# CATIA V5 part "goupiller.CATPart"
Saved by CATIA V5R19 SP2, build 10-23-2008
Part number: Pièce1
Bounding box of the stored display mesh (mm): x 0 to 60, y -7.5 to 7.5, z -7.5 to 7.5
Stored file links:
  C:\Users\marc\Desktop\boulot\Semestre 3\CFAO\Projet CFAO\robuste\goupiller.CATPart
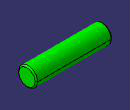
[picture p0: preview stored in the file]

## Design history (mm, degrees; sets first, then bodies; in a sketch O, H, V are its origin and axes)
Parameters
  raytrou = 7.5 mm
  longgoupille = 60 mm
Body1 (main body)
  Sketch1 on yz-plane, origin (0, 0, 0), H (0, 1, 0), V (0, 0, 1)
    circle A1 centre (0, 0) radius 7.5
    radius A1 = 7.5 {= raytrou}
  Pad1: profile Sketch1, direction (1, 0, 0), length 60 {= longgoupille}
  Chamfer1: length 1, angle 45, on edge [face of Pad1 from Sketch1.A1 | end face of Pad1]
  Chamfer2: length 1, angle 45, on edge [start face of Pad1 | face of Pad1 from Sketch1.A1]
